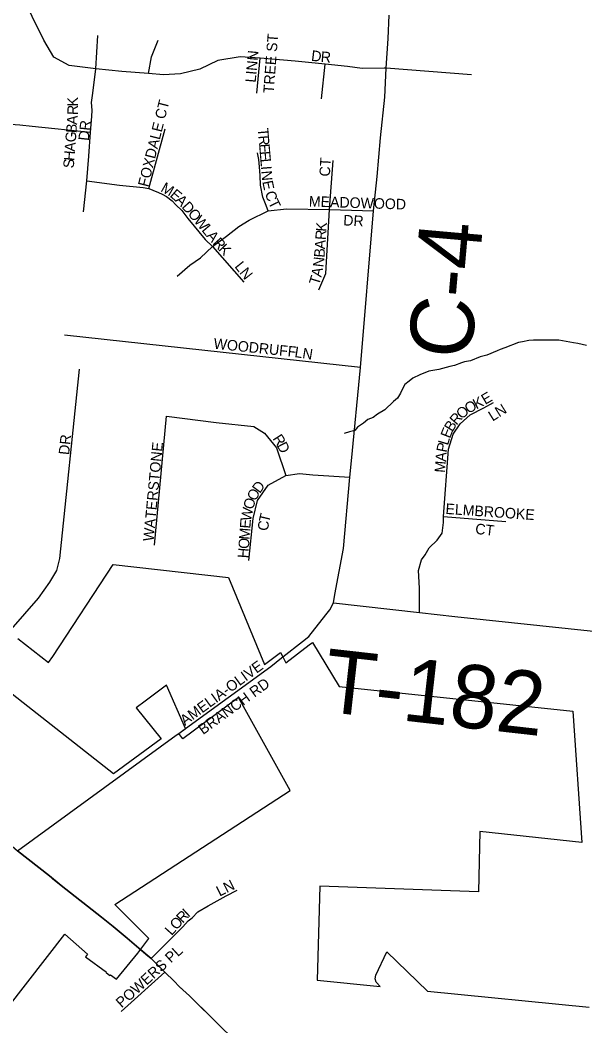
# Model space of a CAD drawing. Extents: x 1310247 to 1664935, y 235267 to 584339.
# Drawn here: x 1476580 to 1479257, y 381993 to 386758 of the extents above; entities that cross this region are included whole.
import ezdxf

# ---------------------------------------------------------------- set-up
doc = ezdxf.new("R2010")
doc.units = 0
for name, color, linetype in [('GM_X_City_Street', 7, 'Continuous'), ('GM_X_City_Street_Text', 7, 'Continuous'), ('GM_X_Corporation', 7, 'Continuous'), ('GM_X_County_Road', 7, 'Continuous'), ('GM_X_County_Road_Text', 7, 'Continuous'), ('GM_X_Minor_River', 7, 'Continuous'), ('GM_X_State_Route', 7, 'Continuous'), ('GM_X_Township', 7, 'Continuous'), ('GM_X_Township_Road', 7, 'Continuous'), ('GM_X_Township_Road_Text', 7, 'Continuous'), ('GM_X_Township_Subdivision', 7, 'Continuous'), ('GM_X_Township_Subdivision_Text', 7, 'Continuous')]:
    doc.layers.add(name, color=color, linetype=linetype)

msp = doc.modelspace()

# ---------------------------------------------------------------- linework, layer by layer
at = {"layer": 'GM_X_City_Street'}
for points in [[(1477362, 383399.7), (1477364.5, 383401.5), (1477769.2, 383696), (1477819.8, 383736.9)], [(1477201.6, 382311.8), (1477352.2, 382461.6), (1477376.5, 382490), (1477396, 382505.3), (1477422.7, 382533.7), (1477472.1, 382561.2), (1477557.1, 382608.2), (1477608.9, 382635.7)], [(1477059.1, 382061.6), (1477266.7, 382247.7)]]:
    msp.add_lwpolyline(points, dxfattribs=at)
at = {"layer": 'GM_X_Corporation'}
for points in [[(1476569.3, 383828.3), (1476715.1, 383713.8), (1476734.6, 383743.3), (1477021.8, 384178.3), (1477567.6, 384116.3), (1477737.9, 383705.5), (1477815, 383761.3), (1477825, 383741.1), (1477840.5, 383713.3), (1477950.9, 383797.7), (1477966.8, 383809.2), (1478092, 383600.9), (1479199.9, 383484.4), (1479243.4, 382861.9), (1478758.8, 382912.9), (1478753.8, 382628.4), (1478001.3, 382654.7), (1477987.9, 382209.2), (1478286.5, 382179.6), (1478268.5, 382200.4), (1478262.8, 382215.6), (1478266.3, 382232.6), (1478319.2, 382343.6), (1478510.6, 382157.4), (1479278.2, 382081.3)], [(1476429.4, 381961.6), (1476792.6, 382426.7), (1476899.8, 382332.1), (1476890.6, 382320.3), (1476990.1, 382247.9), (1476988.8, 382246.4), (1477006.2, 382231.3), (1477008.8, 382234.4), (1477036.3, 382214.4), (1477138.6, 382337.8), (1477190.3, 382406.5), (1477028.4, 382568.4), (1477859.7, 383108.3), (1477615.2, 383549.3), (1477350.9, 383352.1), (1477332.5, 383378.2), (1477364.5, 383401.5), (1477273.7, 383607.4), (1477172.2, 383531.1), (1477130.3, 383499.6), (1477248.6, 383352.8), (1477022.8, 383186.1), (1476430.5, 383651.8)]]:
    msp.add_lwpolyline(points, dxfattribs=at)
at = {"layer": 'GM_X_County_Road'}
for points in [[(1477819.8, 383736.9), (1477825, 383741.1), (1477919.4, 383814.1), (1477949.4, 383837.2), (1478029.8, 383939.7), (1478048.4, 383963.2), (1478065.3, 383996.8), (1478072.4, 384036.7), (1478112.5, 384253.9), (1478143.6, 384591.8), (1478150.8, 384669.6), (1478194, 385111.2), (1478255.3, 385853.6), (1478272.6, 386017.4), (1478288.1, 386199.9), (1478308.7, 386392.8), (1478315.6, 386530.6), (1478324.2, 386670), (1478329.4, 386782)], [(1477320.2, 383369.3), (1477332.5, 383378.2), (1477362, 383399.7)], [(1476567.9, 382821.9), (1477320.2, 383369.3)]]:
    msp.add_lwpolyline(points, dxfattribs=at)
at = {"layer": 'GM_X_Minor_River'}
msp.add_lwpolyline([(1479265.7, 385216.4), (1479223.7, 385225.2), (1479203.7, 385229.5), (1479133.7, 385240.8), (1479085.5, 385241.6), (1479013.2, 385240.9), (1478991.1, 385239.3), (1478960.9, 385233.8), (1478942.8, 385230.1), (1478878.1, 385205.1), (1478855.9, 385197.5), (1478841.8, 385191.7), (1478793.2, 385170.5), (1478761, 385163), (1478714.5, 385143.8), (1478686.3, 385138.2), (1478672.2, 385134.5), (1478639.9, 385121), (1478617.7, 385117.3), (1478565.3, 385102.2), (1478517, 385095), (1478474.5, 385077.7), (1478442.1, 385062.2), (1478423.8, 385046.5), (1478403.5, 385030.8), (1478395.2, 385016.8), (1478382.7, 384991), (1478368.3, 384967.1), (1478350, 384951.4), (1478309.1, 384911.9), (1478274.7, 384890.5), (1478254.3, 384874.7), (1478228.1, 384865.2), (1478207.7, 384847.5), (1478179.3, 384829.9), (1478167, 384814), (1478140.8, 384806.5), (1478116.5, 384798.8)], dxfattribs=at)
at = {"layer": 'GM_X_State_Route'}
for points in [[(1475992.4, 383299.2), (1476044.5, 383257.5), (1476222.8, 383120.6), (1476396.1, 382970.8), (1476567.9, 382821.9), (1476719.8, 382702.9), (1476734, 382691.2)], [(1476734, 382691.2), (1476774.9, 382657.6), (1476965.2, 382507.8), (1477021, 382464), (1477024, 382461.6)], [(1477024, 382461.6), (1477088.2, 382408.2), (1477105, 382393.7)], [(1477105, 382393.7), (1477142.5, 382361.2), (1477185.5, 382325.2)], [(1477185.5, 382325.2), (1477201.6, 382311.8), (1477266.7, 382247.7), (1477310.9, 382204.1), (1477334.4, 382179), (1477336.3, 382177.3)], [(1477336.3, 382177.3), (1477383.4, 382135.6), (1477488.7, 382030.9)], [(1477488.7, 382030.9), (1477528.2, 381991.6), (1477754.3, 381771.4), (1477951.1, 381574.6), (1478200.6, 381332.6), (1478307.7, 381225.7), (1478475.3, 381064), (1478660.5, 380878.8), (1478859.2, 380683.9), (1479019.7, 380524.4), (1479149.1, 380403.4), (1479378.6, 380182.2), (1479559.1, 379991.5)]]:
    msp.add_lwpolyline(points, dxfattribs=at)
at = {"layer": 'GM_X_Township'}
for points in [[(1477528.2, 381991.6), (1477383.4, 382135.6), (1477334.4, 382179), (1477310.9, 382204.1), (1477266.7, 382247.7), (1477201.6, 382311.8), (1477142.5, 382361.2), (1477088.2, 382408.2), (1477021, 382464), (1476965.2, 382507.8), (1476774.9, 382657.6), (1476719.8, 382702.9), (1476567.9, 382821.9)], [(1476567.9, 382821.9), (1476719.8, 382702.9), (1476774.9, 382657.6), (1476965.2, 382507.8), (1477021, 382464), (1477088.2, 382408.2), (1477142.5, 382361.2), (1477201.6, 382311.8), (1477266.7, 382247.7), (1477310.9, 382204.1), (1477334.4, 382179), (1477383.4, 382135.6), (1477528.2, 381991.6)]]:
    msp.add_lwpolyline(points, dxfattribs=at)
at = {"layer": 'GM_X_Township_Road'}
msp.add_lwpolyline([(1478065.3, 383996.8), (1478473.2, 383950.7), (1478641.5, 383931.6), (1479312.4, 383861.9), (1480473.6, 383724.8)], dxfattribs=at)
at = {"layer": 'GM_X_Township_Subdivision'}
for points in [[(1478305.5, 386530.4), (1478202, 386528.8), (1478131.4, 386537.4), (1478026.3, 386549.5), (1477883.4, 386563.3), (1477718.1, 386577), (1477623.4, 386583.9), (1477516.6, 386566.7), (1477431.6, 386524.8), (1477341, 386503), (1477260, 386497.8), (1477189.4, 386504.7), (1477062, 386515), (1476938.6, 386526.5), (1476812.3, 386542.6), (1476740, 386582.2), (1476691.8, 386663.1), (1476581.9, 386888.7)], [(1476880.7, 385849.8), (1476896.5, 385995.8), (1476905.3, 386112.8), (1476913.7, 386227.7), (1476920.5, 386300.9), (1476921.2, 386330.4), (1476918.9, 386367.5), (1476924.2, 386412.2), (1476938.6, 386526.5), (1476949.2, 386685.5)], [(1477189.4, 386504.7), (1477203.2, 386583.9), (1477234.2, 386663.1)], [(1477702.6, 386411.7), (1477718.1, 386577)], [(1478009.1, 386384.2), (1478026.3, 386549.5)], [(1478720.3, 386497.8), (1478315.6, 386530.6), (1478305.5, 386530.4)], [(1475878.9, 386070.8), (1475932.8, 386181.3), (1475946.1, 386205), (1475956.2, 386218.4), (1475967.1, 386231.7), (1475976.7, 386240.4), (1475987.2, 386249.4), (1475995.2, 386255.7), (1476006.5, 386263.6), (1476022, 386272.3), (1476040.1, 386280.1), (1476057.7, 386286), (1476074, 386289.5), (1476091.2, 386292.7), (1476090.8, 386292.3), (1476105.1, 386293.5), (1476115.5, 386293.5), (1476140.7, 386292.3), (1476241.3, 386285.6), (1476578.3, 386260.9), (1476638, 386255), (1476913.7, 386227.7)], [(1477189.7, 385960.6), (1477267.3, 386242.9)], [(1477756.6, 385853.6), (1477743.5, 385887.2), (1477731.2, 385919.1), (1477720.1, 385976.3), (1477717.5, 386021.3), (1477715.3, 386062.1), (1477711.7, 386097.9), (1477705, 386128.8)], [(1477995.8, 385479.2), (1478028.6, 385557.9), (1478046.6, 385860.1), (1478063.8, 386092.8)], [(1476896.5, 385995.8), (1477051.4, 385975.8), (1477163.5, 385964.4), (1477189.7, 385960.6), (1477209.7, 385952), (1477235.8, 385941.4), (1477253, 385933.1), (1477274.4, 385922.5), (1477301.6, 385901.8), (1477318.4, 385883.1), (1477347, 385856), (1477375.7, 385818.4), (1477456.8, 385718.4), (1477492, 385685.6), (1477641.1, 385516.1)], [(1477324.1, 385544.7), (1477384.7, 385596.3), (1477435.5, 385631.6), (1477492, 385685.6), (1477558.4, 385734.8), (1477617.4, 385780.7), (1477666.5, 385809.3), (1477756.6, 385853.6), (1477843.4, 385863.4), (1478046.6, 385860.1), (1478255.3, 385853.6)], [(1478194, 385111.2), (1476790, 385265.6)], [(1476538.4, 383871.1), (1476666.7, 384019.7), (1476720.4, 384094.9), (1476753.8, 384149.7), (1476767.7, 384207.8), (1476861.2, 385103.8)], [(1478473.2, 383950.7), (1478473.5, 384066.9), (1478469.1, 384150), (1478482.2, 384200.3), (1478499.7, 384224.4), (1478519.4, 384257.2), (1478556.6, 384294.4), (1478580.7, 384327.2), (1478587.2, 384377.5), (1478587.2, 384406), (1478611.3, 384725.4), (1478633.2, 384795.5), (1478666, 384845.8), (1478714.1, 384887.4), (1478777.6, 384920.2), (1478823.5, 384946.4)], [(1477216.5, 384270.6), (1477273.4, 384880.8), (1477509.7, 384851.7), (1477687.4, 384832.1), (1477738.9, 384800.1), (1477795.8, 384730.9), (1477839.6, 384600)], [(1477664.3, 384197.8), (1477685.6, 384396.8), (1477705.2, 384482.1), (1477756.7, 384554.9), (1477839.6, 384600), (1477904.5, 384609.3), (1477968.2, 384602.9), (1478143.6, 384591.8)], [(1478587.2, 384406), (1478882.6, 384381.9)]]:
    msp.add_lwpolyline(points, dxfattribs=at)

# ---------------------------------------------------------------- texts
at = {"layer": 'GM_X_City_Street_Text'}
for s, rotation, p in [('AMELIA-OLIVE', 36.0699, (1477361.5, 383413.5)), ('BRANCH RD', 36.0284, (1477447.3, 383370.3)), ('LN', 26.5699, (1477525.6, 382604.7)), ('I', 42.8675, (1477377.7, 382504.5)), ('O', 48.2467, (1477321.8, 382444)), ('R', 46.1334, (1477350.8, 382476.4)), ('L', 48.2666, (1477298.4, 382417.7)), ('POWERS PL', 42.3261, (1477061.5, 382075.2))]:
    msp.add_text(s, height=50, rotation=rotation, dxfattribs=at).set_placement(p)
at = {"layer": 'GM_X_County_Road_Text'}
msp.add_text('C-4', height=300, rotation=84.9719, dxfattribs=at).set_placement((1478717.9, 385146.6))
at = {"layer": 'GM_X_Township_Road_Text'}
msp.add_text('T-182', height=300, rotation=353.5699, dxfattribs=at).set_placement((1478008.2, 383483))
at = {"layer": 'GM_X_Township_Subdivision_Text'}
for s, rotation, p in [('TREE ST', 85.682, (1477782.2, 386409.7)), ('LINN', 84.802, (1477696.5, 386460.3)), ('D', 353.165, (1477957.9, 386565.6)), ('R', 355.325, (1478003.6, 386560.1)), ('R', 89.0678, (1476853.8, 386307.9)), ('K', 90.3645, (1476854.5, 386348.7)), ('FOXDALE CT', 75.9637, (1477186.3, 385964.5)), ('A', 85.5223, (1476850.2, 386260.6)), ('B', 85.5026, (1476847.1, 386221.2)), ('DR', 83.9832, (1476905.6, 386184.5)), ('G', 85.5223, (1476843.7, 386177.3)), ('T', 274.7591, (1477706.4, 386244.6)), ('R', 274.7415, (1477709.3, 386209.5)), ('A', 85.4923, (1476840.2, 386133.4)), ('E', 274.7691, (1477712.6, 386170)), ('H', 85.5141, (1476836.8, 386089.6)), ('E', 274.7319, (1477715.5, 386135)), ('S', 85.5154, (1476834, 386054.5)), ('L', 274.7691, (1477718.4, 386099.8)), ('CT', 86.8215, (1478048.4, 386015.6)), ('I', 274.769, (1477721.3, 386064.8)), ('N', 274.7491, (1477723.2, 386042.8)), ('M', 330.0766, (1477242.9, 385949)), ('E', 281.9241, (1477727.8, 385992.2)), ('E', 319.5054, (1477286.7, 385924.1)), ('A', 314.7991, (1477312.7, 385902)), ('C', 287.7692, (1477739.9, 385939.6)), ('MEADOWOOD', 358.1713, (1477948.4, 385874.8)), ('D', 311.8296, (1477343.2, 385871.3)), ('T', 295.9997, (1477754.9, 385894.7)), ('O', 310.4353, (1477372.3, 385838.7)), ('W', 310.2512, (1477400.9, 385805.3)), ('DR', 356.9776, (1478111, 385785.5)), ('L', 310.2497, (1477437.8, 385761.6)), ('K', 85.9127, (1478031.6, 385754.4)), ('A', 310.3963, (1477460.6, 385734.6)), ('R', 85.9127, (1478028.8, 385714.9)), ('R', 312.198, (1477490.3, 385699.8)), ('K', 313.2158, (1477517.6, 385669.8)), ('A', 85.9127, (1478025.7, 385671)), ('B', 85.9127, (1478022.9, 385631.5)), ('LN', 308.6545, (1477594.4, 385589.7)), ('N', 83.354, (1478017.5, 385585.4)), ('T', 73.1193, (1477996.4, 385499.1)), ('A', 78.2367, (1478007.8, 385537.5)), ('WOODRUFF', 354.0689, (1477495.6, 385201.6)), ('LN', 351.0327, (1477878.9, 385161.9)), ('K', 26.9756, (1478742.6, 384912.7)), ('E', 30.6689, (1478784.9, 384934.4)), ('O', 40.8549, (1478673.5, 384864.4)), ('O', 28.9803, (1478704.5, 384891.6)), ('LN', 32.0029, (1478819.5, 384855.3)), ('R', 49.0905, (1478648.9, 384835.8)), ('E', 68.4015, (1478617.5, 384773.1)), ('B', 58.3782, (1478629.4, 384803.8)), ('DR', 83.9946, (1476812.1, 384696)), ('R', 302.6798, (1477775.1, 384775.3)), ('WATERSTONE', 84.5317, (1477212.5, 384286.7)), ('D', 296.9268, (1477795.8, 384743.1)), ('P', 78.8669, (1478601.5, 384707.1)), ('L', 73.7168, (1478608, 384740.5)), ('A', 85.4487, (1478598.2, 384664.8)), ('M', 85.4602, (1478594, 384612.1)), ('D', 53.3924, (1477715.9, 384512.6)), ('O', 74.2197, (1477684.3, 384436.3)), ('O', 60.3446, (1477695, 384475.7)), ('W', 79.0033, (1477673.6, 384381.2)), ('ELMBROOKE', 356.0087, (1478595.3, 384418.4)), ('T', 76.4873, (1477759.7, 384374.1)), ('M', 85.9351, (1477667.5, 384295.1)), ('E', 85.7333, (1477671.2, 384347.7)), ('C', 83.7939, (1477755.7, 384336.4)), ('CT', 353.6518, (1478735.7, 384324.1)), ('O', 85.939, (1477664.3, 384251.2)), ('H', 85.9315, (1477661.2, 384207.3))]:
    msp.add_text(s, height=50, rotation=rotation, dxfattribs=at).set_placement(p)

doc.saveas('drawing.dxf')
